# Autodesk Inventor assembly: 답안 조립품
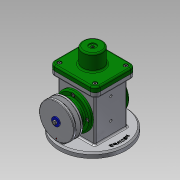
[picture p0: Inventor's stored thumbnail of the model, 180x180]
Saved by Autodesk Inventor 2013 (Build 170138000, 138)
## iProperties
Created: 2005-01
Part Number: 답안 조립품
Document SubType Name: Assembly
Designer: hana-cad36
Author: hana-cad36
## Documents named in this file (18)
- C:\Documents and Settings\hana-cad36\바탕 화면\490804V1032\답안 조립품.iam
- C:\Documents and Settings\hana-cad36\바탕 화면\490804V1032\본체.ipt
- C:\Documents and Settings\hana-cad36\바탕 화면\490804V1032\편심축.ipt
- C:\Documents and Settings\hana-cad36\바탕 화면\490804V1032\베어링 17 x 40 x 12.ipt
- C:\Documents and Settings\hana-cad36\바탕 화면\490804V1032\앞커버.ipt
- C:\Documents and Settings\hana-cad36\바탕 화면\490804V1032\클레비스 핀 6 x 22.ipt
- 클레비스 핀 6 x 22.ipt
- C:\Documents and Settings\hana-cad36\바탕 화면\490804V1032\슬라이더.ipt
- C:\Documents and Settings\hana-cad36\바탕 화면\490804V1032\링크.ipt
- C:\Documents and Settings\hana-cad36\바탕 화면\490804V1032\덮개.ipt
- C:\Documents and Settings\hana-cad36\바탕 화면\490804V1032\E-링.ipt
- C:\Documents and Settings\hana-cad36\바탕 화면\490804V1032\오일 실 17 30 8.ipt
- C:\Documents and Settings\hana-cad36\바탕 화면\490804V1032\키 4 x 4 x 12.ipt
- C:\Documents and Settings\hana-cad36\바탕 화면\490804V1032\V-벨트풀리.ipt
- C:\Documents and Settings\hana-cad36\바탕 화면\490804V1032\와셔 4x16.ipt
- C:\Documents and Settings\hana-cad36\바탕 화면\490804V1032\볼트 M4 x 10.ipt
- C:\Documents and Settings\hana-cad36\바탕 화면\490804V1032\뒤커버.ipt
- C:\Documents and Settings\hana-cad36\바탕 화면\490804V1032\볼트 M4 x 8.ipt
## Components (2 placed, 2 different names)
1. E-링:1
2. V-벨트풀리:1 — 각도:2
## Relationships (1: Angle 1)
- 각도:2 [Angle]: V-벨트풀리:1
